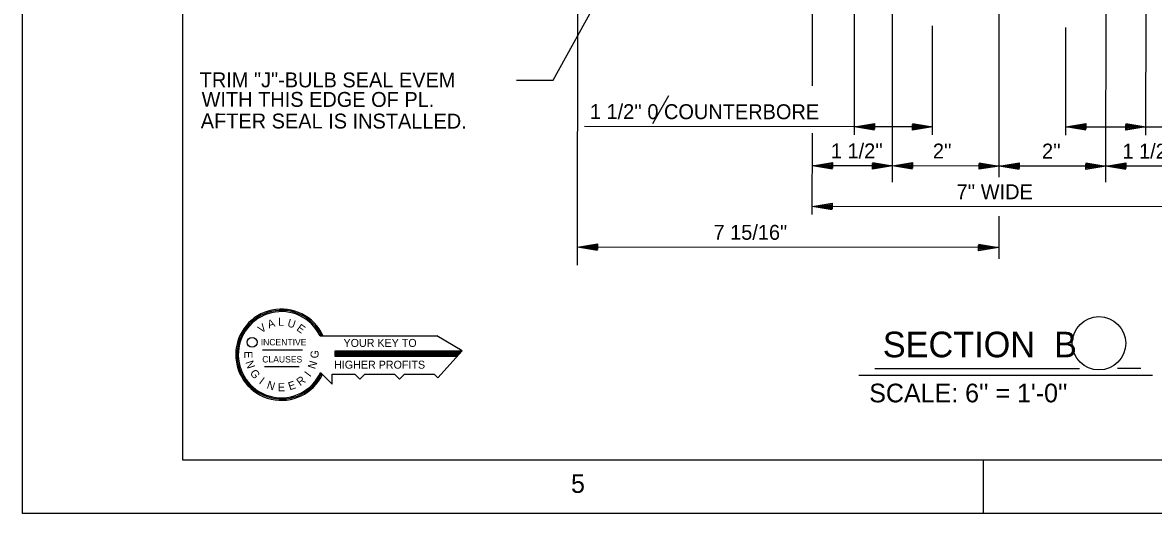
# Model space of a CAD drawing. Extents: x 0.04 to 6.71, y 0.04 to 4.71.
# Drawn here: x 0.042 to 1.808, y 0.042 to 0.809 of the extents above; entities that cross this region are included whole.
import ezdxf

# ---------------------------------------------------------------- set-up
doc = ezdxf.new("R2010")
doc.units = 0
for name, color, linetype in [('Level 1', 7, 'Continuous'), ('Level 25', 7, 'Continuous'), ('Level 3', 7, 'Continuous'), ('Level 50', 7, 'Continuous')]:
    doc.layers.add(name, color=color, linetype=linetype)

msp = doc.modelspace()

# ---------------------------------------------------------------- linework, layer by layer
at = {"layer": 'Level 1'}
for p, q in [((0.5063, 0.3193), (0.6884, 0.3193)), ((0.7281, 0.2958), (0.6884, 0.3193)), ((0.4163, 0.2974), (0.4786, 0.2974)), ((0.7276, 0.2951), (0.5294, 0.2951)), ((0.5294, 0.2951), (0.5294, 0.2874)), ((0.7256, 0.293), (0.5294, 0.293)), ((0.7239, 0.291), (0.5294, 0.291)), ((0.722, 0.2889), (0.5294, 0.2889)), ((0.5294, 0.2874), (0.7206, 0.2874)), ((0.7281, 0.2958), (0.6903, 0.2534)), ((0.4195, 0.271), (0.4735, 0.271)), ((0.5071, 0.2618), (0.5253, 0.2436)), ((0.5253, 0.2436), (0.5253, 0.2593)), ((0.5253, 0.2593), (0.5604, 0.2593)), ((0.5604, 0.2593), (0.5681, 0.2515)), ((0.5681, 0.2515), (0.5759, 0.2593)), ((0.5759, 0.2593), (0.6224, 0.2593)), ((0.6224, 0.2593), (0.6301, 0.2515)), ((0.6301, 0.2515), (0.6379, 0.2593)), ((0.6379, 0.2593), (0.6844, 0.2593)), ((0.6844, 0.2593), (0.6903, 0.2534)), ((1.5417, 0.125), (1.5417, 0.0417))]:
    msp.add_line(p, q, dxfattribs=at)
for points in [[(0.0417, 4.7083), (6.7083, 4.7083), (6.7083, 0.0417), (0.0417, 0.0417)], [(0.2917, 4.625), (6.625, 4.625), (6.625, 0.125), (0.2917, 0.125)]]:
    msp.add_lwpolyline(points, close=True, dxfattribs=at)
msp.add_circle((0.4001, 0.309), 0.00769, dxfattribs=at)
for radius, start, end in [(0.0713, 24.569, 334.4243), (0.0693, 25.3095, 334.4522), (0.0673, 26.0896, 335.5943)]:
    msp.add_arc((0.4458, 0.2897), radius, start, end, dxfattribs=at)
at = {"layer": 'Level 25'}
for p, q in [((1.4, 0.5594), (1.4009, 1.5458)), ((1.7333, 0.5591), (1.7342, 1.5051)), ((0.8703, 0.7184), (1.2307, 1.3763)), ((1.5667, 0.567), (1.5673, 1.2927)), ((0.9081, 0.4296), (0.9089, 1.2759)), ((1.2751, 0.7096), (1.2752, 0.8598)), ((1.3406, 0.6332), (1.3408, 0.8394)), ((1.7959, 0.6328), (1.7961, 0.8292)), ((1.4626, 0.6331), (1.4627, 0.8038)), ((1.6709, 0.6329), (1.671, 0.8012)), ((0.8129, 0.7184), (0.8703, 0.7184)), ((1.0258, 0.651), (1.051, 0.6947)), ((1.3406, 0.6459), (0.919, 0.6462)), ((1.2749, 0.5085), (1.2751, 0.6358)), ((1.3406, 0.6459), (1.3406, 0.6459)), ((1.4626, 0.6458), (1.3406, 0.6459)), ((1.6709, 0.6458), (1.7959, 0.6459)), ((1.7959, 0.6459), (2.2213, 0.6462)), ((1.7959, 0.6459), (1.7959, 0.6459)), ((1.4, 0.5847), (1.275, 0.5848)), ((1.3405, 0.5847), (1.3405, 0.5847)), ((1.4, 0.5847), (1.4, 0.5847)), ((1.5667, 0.5845), (1.4, 0.5847)), ((1.5667, 0.5845), (1.5667, 0.5845)), ((1.7333, 0.5844), (1.5667, 0.5845)), ((1.7333, 0.5844), (1.7333, 0.5844)), ((1.8583, 0.5843), (1.7333, 0.5844)), ((1.8583, 0.5207), (1.2749, 0.5212)), ((1.5666, 0.4397), (1.5666, 0.5059)), ((1.5666, 0.4573), (0.9081, 0.4578))]:
    msp.add_line(p, q, dxfattribs=at)
at = {"layer": 'Level 3'}
for p, q in [((1.3724, 0.2681), (1.6922, 0.2681)), ((1.7879, 0.2681), (1.7514, 0.2681)), ((1.3474, 0.2577), (1.8064, 0.2577))]:
    msp.add_line(p, q, dxfattribs=at)
msp.add_circle((1.7226, 0.3075), 0.0417, dxfattribs=at)
at = {"layer": 'Level 50'}
for p, q in [((1.3406, 0.6459), (1.3406, 0.6459)), ((1.3493, 0.6459), (1.3493, 0.6459)), ((1.4539, 0.6458), (1.4539, 0.6458)), ((1.4626, 0.6458), (1.4626, 0.6458)), ((1.6709, 0.6458), (1.6709, 0.6458)), ((1.6796, 0.6458), (1.6796, 0.6458)), ((1.7872, 0.6459), (1.7872, 0.6459)), ((1.7959, 0.6459), (1.7959, 0.6459)), ((1.275, 0.5848), (1.275, 0.5848)), ((1.2837, 0.5848), (1.2837, 0.5848)), ((1.3914, 0.5847), (1.3914, 0.5847)), ((1.4, 0.5847), (1.4, 0.5847)), ((1.4, 0.5847), (1.4, 0.5847)), ((1.4087, 0.5847), (1.4087, 0.5847)), ((1.558, 0.5846), (1.558, 0.5846)), ((1.5667, 0.5845), (1.5667, 0.5845)), ((1.5667, 0.5845), (1.5667, 0.5845)), ((1.5754, 0.5845), (1.5754, 0.5845)), ((1.7247, 0.5844), (1.7247, 0.5844)), ((1.7333, 0.5844), (1.7333, 0.5844)), ((1.7333, 0.5844), (1.7333, 0.5844)), ((1.742, 0.5844), (1.742, 0.5844)), ((1.2749, 0.5212), (1.2749, 0.5212)), ((1.2836, 0.5212), (1.2836, 0.5212)), ((0.9081, 0.4578), (0.9081, 0.4578)), ((0.9168, 0.4578), (0.9168, 0.4578)), ((1.5568, 0.4573), (1.5568, 0.4573)), ((1.5655, 0.4573), (1.5655, 0.4573))]:
    msp.add_line(p, q, dxfattribs=at)
for points in [[(1.3718, 0.6407), (1.3406, 0.6459), (1.3718, 0.651), (1.3718, 0.6422), (1.3493, 0.6459), (1.3704, 0.6493), (1.3704, 0.6437), (1.3576, 0.6459), (1.3691, 0.6477), (1.3691, 0.6453), (1.3663, 0.6458)], [(1.4314, 0.651), (1.4626, 0.6458), (1.4314, 0.6406), (1.4314, 0.6495), (1.4539, 0.6458), (1.4327, 0.6423), (1.4327, 0.6479), (1.4456, 0.6458), (1.4341, 0.6439), (1.4341, 0.6463), (1.4369, 0.6458)], [(1.7021, 0.6406), (1.6709, 0.6458), (1.7021, 0.6509), (1.7021, 0.6421), (1.6796, 0.6458), (1.7007, 0.6493), (1.7007, 0.6436), (1.6879, 0.6458), (1.6994, 0.6476), (1.6994, 0.6453), (1.6966, 0.6458)], [(1.7647, 0.651), (1.7959, 0.6459), (1.7647, 0.6407), (1.7647, 0.6495), (1.7872, 0.6459), (1.7661, 0.6423), (1.7661, 0.648), (1.7789, 0.6459), (1.7674, 0.644), (1.7674, 0.6463), (1.7702, 0.6458)], [(1.3062, 0.5796), (1.275, 0.5848), (1.3062, 0.5899), (1.3062, 0.5811), (1.2837, 0.5848), (1.3048, 0.5883), (1.3048, 0.5826), (1.292, 0.5848), (1.3035, 0.5866), (1.3035, 0.5843), (1.3007, 0.5848)], [(1.3689, 0.5899), (1.4, 0.5847), (1.3689, 0.5796), (1.3689, 0.5884), (1.3914, 0.5847), (1.3702, 0.5812), (1.3702, 0.5869), (1.383, 0.5847), (1.3715, 0.5829), (1.3715, 0.5852), (1.3744, 0.5847)], [(1.4312, 0.5795), (1.4, 0.5847), (1.4312, 0.5898), (1.4312, 0.581), (1.4087, 0.5847), (1.4299, 0.5882), (1.4299, 0.5825), (1.417, 0.5847), (1.4285, 0.5865), (1.4285, 0.5842), (1.4257, 0.5847)], [(1.5355, 0.5897), (1.5667, 0.5845), (1.5355, 0.5794), (1.5355, 0.5882), (1.558, 0.5846), (1.5369, 0.5811), (1.5369, 0.5867), (1.5497, 0.5846), (1.5382, 0.5827), (1.5382, 0.5851), (1.541, 0.5846)], [(1.5979, 0.5793), (1.5667, 0.5845), (1.5979, 0.5897), (1.5979, 0.5808), (1.5754, 0.5845), (1.5965, 0.588), (1.5965, 0.5823), (1.5837, 0.5845), (1.5952, 0.5864), (1.5952, 0.584), (1.5924, 0.5845)], [(1.7022, 0.5896), (1.7333, 0.5844), (1.7022, 0.5793), (1.7022, 0.5881), (1.7247, 0.5844), (1.7035, 0.5809), (1.7035, 0.5866), (1.7163, 0.5844), (1.7048, 0.5826), (1.7048, 0.5849), (1.7077, 0.5844)], [(1.7645, 0.5792), (1.7333, 0.5844), (1.7645, 0.5895), (1.7645, 0.5807), (1.742, 0.5844), (1.7632, 0.5879), (1.7632, 0.5822), (1.7503, 0.5844), (1.7618, 0.5862), (1.7618, 0.5839), (1.759, 0.5844)], [(1.3061, 0.516), (1.2749, 0.5212), (1.3061, 0.5263), (1.3061, 0.5175), (1.2836, 0.5212), (1.3048, 0.5246), (1.3048, 0.519), (1.2919, 0.5212), (1.3034, 0.523), (1.3034, 0.5206), (1.3006, 0.5211)], [(0.9393, 0.4526), (0.9081, 0.4578), (0.9393, 0.463), (0.9393, 0.4541), (0.9168, 0.4578), (0.9379, 0.4613), (0.9379, 0.4556), (0.9251, 0.4578), (0.9366, 0.4596), (0.9366, 0.4573), (0.9338, 0.4578)], [(1.5343, 0.4625), (1.5655, 0.4573), (1.5343, 0.4521), (1.5343, 0.461), (1.5568, 0.4573), (1.5356, 0.4538), (1.5356, 0.4595), (1.5485, 0.4573), (1.537, 0.4554), (1.537, 0.4578), (1.5398, 0.4573)]]:
    msp.add_lwpolyline(points, dxfattribs=at)

# ---------------------------------------------------------------- texts
at = {"layer": 'Level 1'}
for s, rotation, p in [('V', 35.9204, (0.4146, 0.3226)), ('A', 18.0731, (0.4263, 0.3306)), ('U', 342.1107, (0.4541, 0.3343)), ('E', 323.9298, (0.4684, 0.3286)), ('E', 270, (0.3881, 0.2951)), ('G', 90, (0.5039, 0.2839)), ('N', 288.0821, (0.3895, 0.2781)), ('G', 306.0537, (0.3959, 0.2611)), ('N', 71.9179, (0.4984, 0.2663)), ('I', 323.5836, (0.4098, 0.2453)), ('N', 341.9179, (0.422, 0.2374)), ('E', 18.2241, (0.4588, 0.2339)), ('R', 36.2206, (0.4751, 0.2403)), ('I', 53.5836, (0.4906, 0.254))]:
    msp.add_text(s, height=0.0125, rotation=rotation, dxfattribs=at).set_placement(p)
for s, height, p in [('L', 0.0125, (0.4406, 0.3348)), ('INCENTIVE', 0.01, (0.4135, 0.3043)), ('YOUR KEY TO', 0.0125, (0.5428, 0.3018)), ('CLAUSES', 0.01, (0.4159, 0.2775)), ('HIGHER PROFITS', 0.0125, (0.5281, 0.2678)), ('E', 0.0125, (0.4404, 0.2325)), ('5', 0.0292, (0.8981, 0.0737))]:
    msp.add_text(s, height=height, dxfattribs=at).set_placement(p)
at = {"layer": 'Level 25'}
for s, height, rotation, p in [('TRIM "J"-BULB SEAL EVEM', 0.023292, 359.9499, (0.3182, 0.7076)), ('WITH THIS EDGE OF PL.', 0.023292, 359.9499, (0.3212, 0.6771)), ("1 1/2'' 0 COUNTERBORE", 0.023292, 359.9504, (0.9275, 0.6579)), ('AFTER SEAL IS INSTALLED.', 0.023292, 359.9499, (0.3198, 0.6433)), ("1 1/2''", 0.02329, 359.9545, (1.3039, 0.5965)), ("2''", 0.02329, 359.9499, (1.4632, 0.5963)), ("2''", 0.02329, 359.9499, (1.6336, 0.5962)), ("1 1/2''", 0.02329, 359.9523, (1.7592, 0.5961)), ("7'' WIDE", 0.02329, 359.9499, (1.5001, 0.5327)), ('7 15/16"', 0.02329, 359.9502, (1.1206, 0.4693))]:
    msp.add_text(s, height=height, rotation=rotation, dxfattribs=at).set_placement(p)
msp.add_text("SCALE: 6'' = 1'-0''", height=0.029198, dxfattribs=at).set_placement((1.3638, 0.2152))
at = {"layer": 'Level 3'}
msp.add_text('SECTION  B', height=0.04, dxfattribs=at).set_placement((1.385, 0.2856))

doc.saveas('drawing.dxf')
